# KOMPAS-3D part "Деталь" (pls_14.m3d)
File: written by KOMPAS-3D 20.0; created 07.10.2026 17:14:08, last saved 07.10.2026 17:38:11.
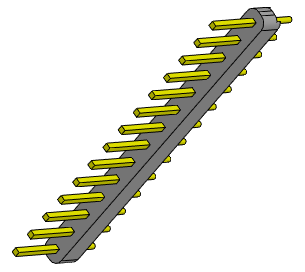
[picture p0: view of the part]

Document properties: Полное имя файла: D:\myProjects\Progect_esp32\box_compas\разъемы\pls_14.m3d

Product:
- Part/product: Деталь
    Масса: 0.00180884
  - Body: Тело 1
      Масса: 0.00182492

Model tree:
1. Эскиз:1
2. Элемент выдавливания:1
     Расстояние 1 = 2.5
3. Эскиз:2  (with: Элемент выдавливания:1)
4. Элемент выдавливания:2
     Расстояние 1 = 6
5. Массив по сетке:1  (with: Элемент выдавливания:2, Эскиз:2)  (14 pattern instances)
     Шаг 1 = 2.54; Угол раствора = 90
6. Эскиз:3  (with: Элемент выдавливания:1)
7. Элемент выдавливания:3
     Расстояние 1 = 3
8. Массив по сетке:2  (with: Элемент выдавливания:3, Эскиз:3)  (14 pattern instances)
     Шаг 1 = 2.54; Угол раствора = 90; Геометрический массив = 128
9. Эскиз:4  (with: Элемент выдавливания:1)
10. Элемент выдавливания:4
     Расстояние 2 = 35.56
11. Скругление:1  (with: Элемент выдавливания:1)
     Радиус = 1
